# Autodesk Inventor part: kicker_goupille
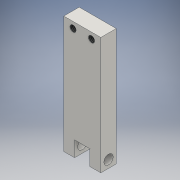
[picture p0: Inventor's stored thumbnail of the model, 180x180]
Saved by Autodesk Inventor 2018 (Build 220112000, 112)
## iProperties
Created: 2018-03
Part Number: kicker_goupille
Material: Iron, Ductile
Document SubType Name: Modeling
Designer: Gregwar
Density: 7.15 g/cm^3
Appearance: Iron Gray
Mass: 15.0545 g
Surface Area: 14.497 cm^2
Volume: 2.10552 cm^3
Author: Gregwar
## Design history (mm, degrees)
sketch "Esquisse1"
  geometry: L1 (0, 0)-(12, 0); L2 (12, 0)-(12, -38); L3 (12, -38)-(0, -38); L4 (0, -38)-(0, 0)
  constraints: 8 end point, 2 parallel, 1 horizontal, 1 perpendicular
  dimensions: "d0" = 12 distance of L1.start L1.end; "d1" = 38 distance of L3.end L1.start
extrude "Extrusion1" new body sketch "Esquisse1" distance "d2" = 5; taper "d3" = 0 deg
sketch "Esquisse2"
  geometry: L1 (-12, 0)-(0, 0) reference; L2 (0, 0)-(0, 38) reference; L3 (0, 38)-(-12, 38) reference; L4 (-12, 38)-(-12, 0) reference; L5 (-8.5, 38)-(-3.5, 38); L6 (-3.5, 38)-(-3.5, 33); L7 (-3.5, 33)-(-8.5, 33); L8 (-8.5, 33)-(-8.5, 38); 2 further points
  constraints: 8 end point, 2 midpoint, 2 parallel, 1 horizontal, 1 perpendicular
  dimensions: "d4" = 5 distance between parallel lines of L6 L8; "d5" = 5 distance of L7.end L5.start
extrude "Extrusion2" cut sketch "Esquisse2" extent not by distance; stored distance "d6" = 5; taper "d7" = 0 deg
sketch "Esquisse3"
  geometry: L1 (5, -5)-(0, -5) reference; L2 (5, 0)-(5, -5) reference; L3 (0, 0)-(5, 0) reference; L4 (0, 0)-(0, -5) reference; L5 (0, -2.5)-(5, -2.5); C1 r 1.5 at (2.5, -2.5); 1 further point
  constraints: 3 midpoint, 2 end point, 1 centre point
  dimensions: "d8" = 3 diameter of C1
extrude "Extrusion3" cut sketch "Esquisse3" extent not by distance; stored distance "d9" = 5; taper "d10" = 0 deg
sketch "Sketch4"
  geometry: L1 (-18.325, -2)-(6.518, -2); L2 (-12, 0)-(0, 0) reference; L3 (-6, 0)-(-6, -7.461); L4 (-9, 0)-(-9, -6.559); 2 further points
  constraints: 6 end point, 3 point on line, 2 vertical, 1 horizontal, 1 midpoint, 1 symmetric about line
  dimensions: "d11" = 2 distance between parallel lines of L2 L1; "d12" = 3 distance between parallel lines of L3 L4
hole "Hole1" sketch "Sketch4" at (-9, -2), (-3, -2) diameter "d13" = 2.013; stored, may be unused: countersink angle "d17" = 90 deg, drill point angle "d19" = 118 deg; dims "d14" = 5, "d15" = 4, "d16" = 2, "d18" = 7.6
node "Solide1"
node "Boucle projetée1"
node "Boucle projetée2"
